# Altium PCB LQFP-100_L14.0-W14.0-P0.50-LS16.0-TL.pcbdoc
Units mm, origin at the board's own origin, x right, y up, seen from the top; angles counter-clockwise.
Board outline 29.8 x 29.8 mm, 2 copper layers (Top Layer, Bottom Layer), stack 0 mm thick; 1 components, 0 nets, 100 pads, 0 vias.
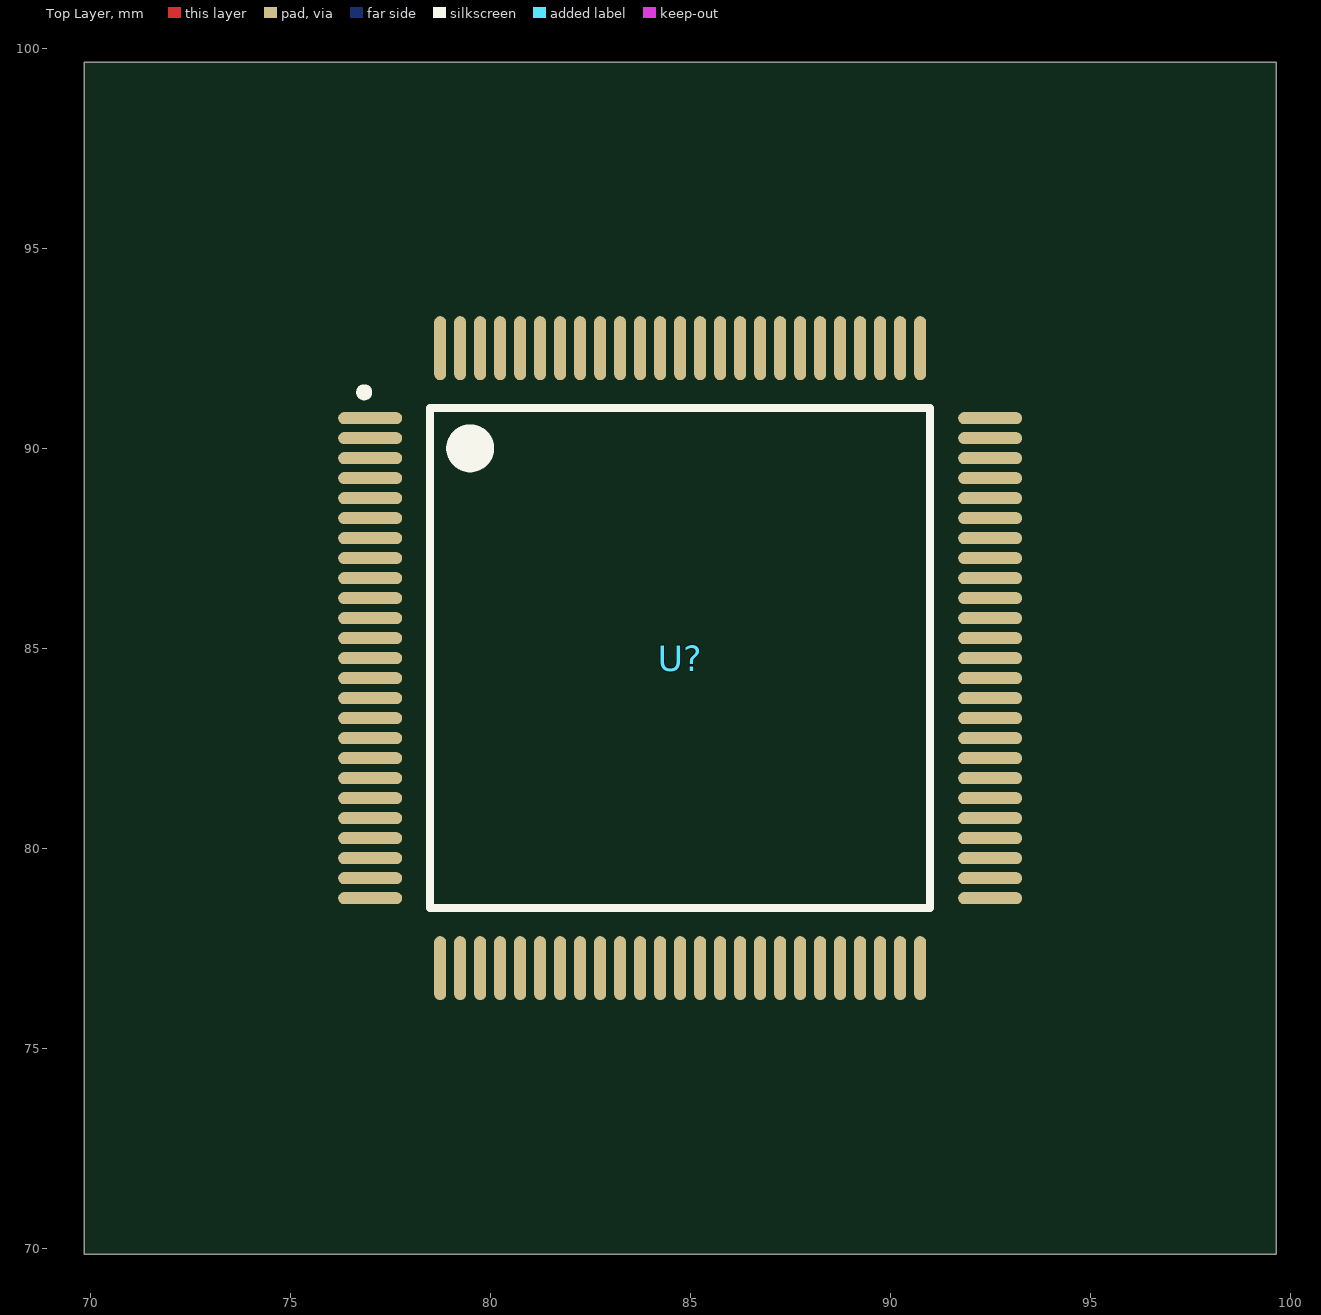
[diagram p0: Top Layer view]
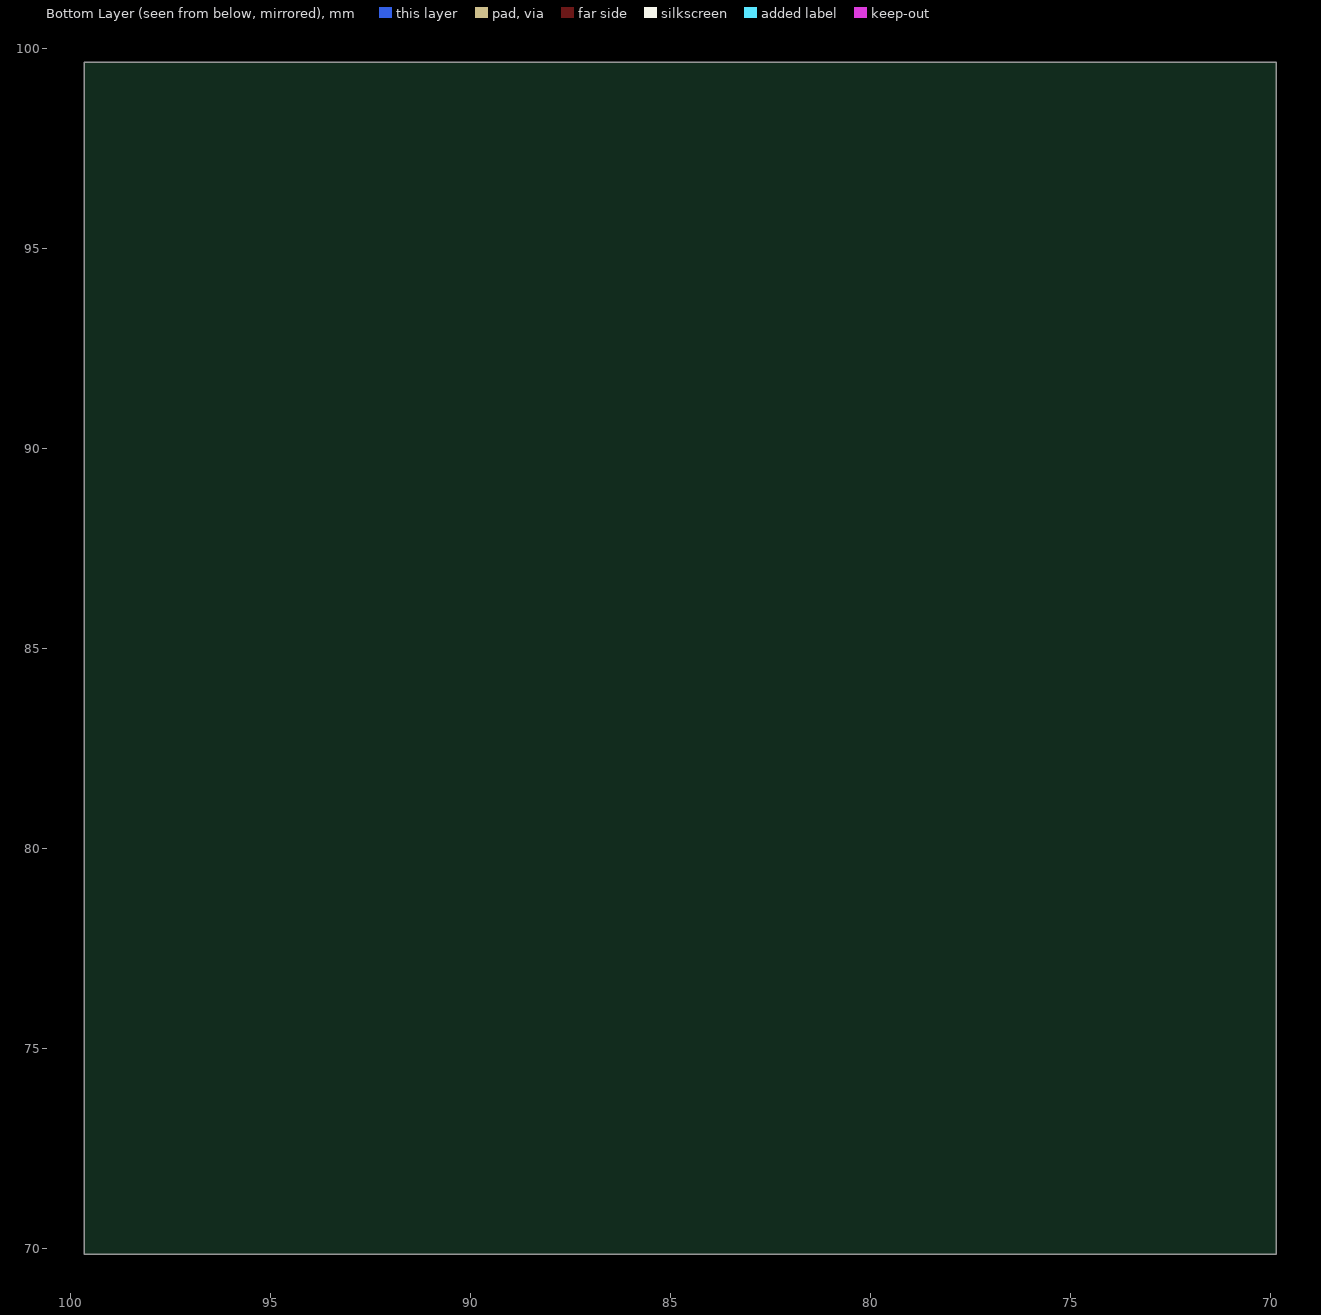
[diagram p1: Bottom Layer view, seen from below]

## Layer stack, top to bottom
Top Layer: signal copper (thickness not stored)
Bottom Layer: signal copper (thickness not stored)

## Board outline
99.65,69.85 69.85,69.85 69.85,99.65 99.65,99.65

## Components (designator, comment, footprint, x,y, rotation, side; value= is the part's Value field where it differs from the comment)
U? "" LQFP-100_L14.0-W14.0-P0.50-LS16.0-TL 84.75,84.75 r0 top

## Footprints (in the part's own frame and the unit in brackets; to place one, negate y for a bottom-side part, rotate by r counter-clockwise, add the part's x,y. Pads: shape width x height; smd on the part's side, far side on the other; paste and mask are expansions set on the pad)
LQFP-100_L14.0-W14.0-P0.50-LS16.0-TL [mm]
  oval 1.6x0.3 smd: 1(-7.75,6) 2(-7.75,5.5) 3(-7.75,5) 4(-7.75,4.5) 5(-7.75,4) 6(-7.75,3.5) 7(-7.75,3) 8(-7.75,2.5) 9(-7.75,2) 10(-7.75,1.5) 11(-7.75,1) 12(-7.75,0.5) 13(-7.75,0) 14(-7.75,-0.5) 15(-7.75,-1) 16(-7.75,-1.5) 17(-7.75,-2) 18(-7.75,-2.5) 19(-7.75,-3) 20(-7.75,-3.5) 21(-7.75,-4) 22(-7.75,-4.5) 23(-7.75,-5) 24(-7.75,-5.5) 25(-7.75,-6) 51(7.75,-6) 52(7.75,-5.5) 53(7.75,-5) 54(7.75,-4.5) 55(7.75,-4) 56(7.75,-3.5) 57(7.75,-3) 58(7.75,-2.5) 59(7.75,-2) 60(7.75,-1.5) 61(7.75,-1) 62(7.75,-0.5) 63(7.75,0) 64(7.75,0.5) 65(7.75,1) 66(7.75,1.5) 67(7.75,2) 68(7.75,2.5) 69(7.75,3) 70(7.75,3.5) 71(7.75,4) 72(7.75,4.5) 73(7.75,5) 74(7.75,5.5) 75(7.75,6)
  oval 0.3x1.6 smd: 26(-6,-7.75) 27(-5.5,-7.75) 28(-5,-7.75) 29(-4.5,-7.75) 30(-4,-7.75) 31(-3.5,-7.75) 32(-3,-7.75) 33(-2.5,-7.75) 34(-2,-7.75) 35(-1.5,-7.75) 36(-1,-7.75) 37(-0.5,-7.75) 38(0,-7.75) 39(0.5,-7.75) 40(1,-7.75) 41(1.5,-7.75) 42(2,-7.75) 43(2.5,-7.75) 44(3,-7.75) 45(3.5,-7.75) 46(4,-7.75) 47(4.5,-7.75) 48(5,-7.75) 49(5.5,-7.75) 50(6,-7.75) 76(6,7.75) 77(5.5,7.75) 78(5,7.75) 79(4.5,7.75) 80(4,7.75) 81(3.5,7.75) 82(3,7.75) 83(2.5,7.75) 84(2,7.75) 85(1.5,7.75) 86(1,7.75) 87(0.5,7.75) 88(0,7.75) 89(-0.5,7.75) 90(-1,7.75) 91(-1.5,7.75) 92(-2,7.75) 93(-2.5,7.75) 94(-3,7.75) 95(-3.5,7.75) 96(-4,7.75) 97(-4.5,7.75) 98(-5,7.75) 99(-5.5,7.75) 100(-6,7.75)
  silkscreen extent -8,-6.25 6.25,6.75

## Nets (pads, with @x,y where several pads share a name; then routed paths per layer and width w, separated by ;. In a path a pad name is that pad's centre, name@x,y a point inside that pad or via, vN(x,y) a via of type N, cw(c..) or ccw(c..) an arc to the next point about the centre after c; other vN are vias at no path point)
pads on no net: U?.1 U?.2 U?.3 U?.4 U?.5 U?.6 U?.7 U?.8 U?.9 U?.10 U?.11 U?.12 U?.13 U?.14 U?.15 U?.16 U?.17 U?.18 U?.19 U?.20 U?.21 U?.22 U?.23 U?.24 U?.25 U?.26 U?.27 U?.28 U?.29 U?.30 U?.31 U?.32 U?.33 U?.34 U?.35 U?.36 U?.37 U?.38 U?.39 U?.40 U?.41 U?.42 U?.43 U?.44 U?.45 U?.46 U?.47 U?.48 U?.49 U?.50 U?.51 U?.52 U?.53 U?.54 U?.55 U?.56 U?.57 U?.58 U?.59 U?.60 U?.61 U?.62 U?.63 U?.64 U?.65 U?.66 U?.67 U?.68 U?.69 U?.70 U?.71 U?.72 U?.73 U?.74 U?.75 U?.76 U?.77 U?.78 U?.79 U?.80 U?.81 U?.82 U?.83 U?.84 U?.85 U?.86 U?.87 U?.88 U?.89 U?.90 U?.91 U?.92 U?.93 U?.94 U?.95 U?.96 U?.97 U?.98 U?.99 U?.100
